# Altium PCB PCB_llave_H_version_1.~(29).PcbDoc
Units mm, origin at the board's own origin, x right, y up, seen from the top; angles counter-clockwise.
Board outline 232.16 x 155.45 mm, 2 copper layers (Top Layer, Bottom Layer); 51 components, 32 nets, 157 pads, 0 vias.
Unrouted connection lines stored in the file: 57.
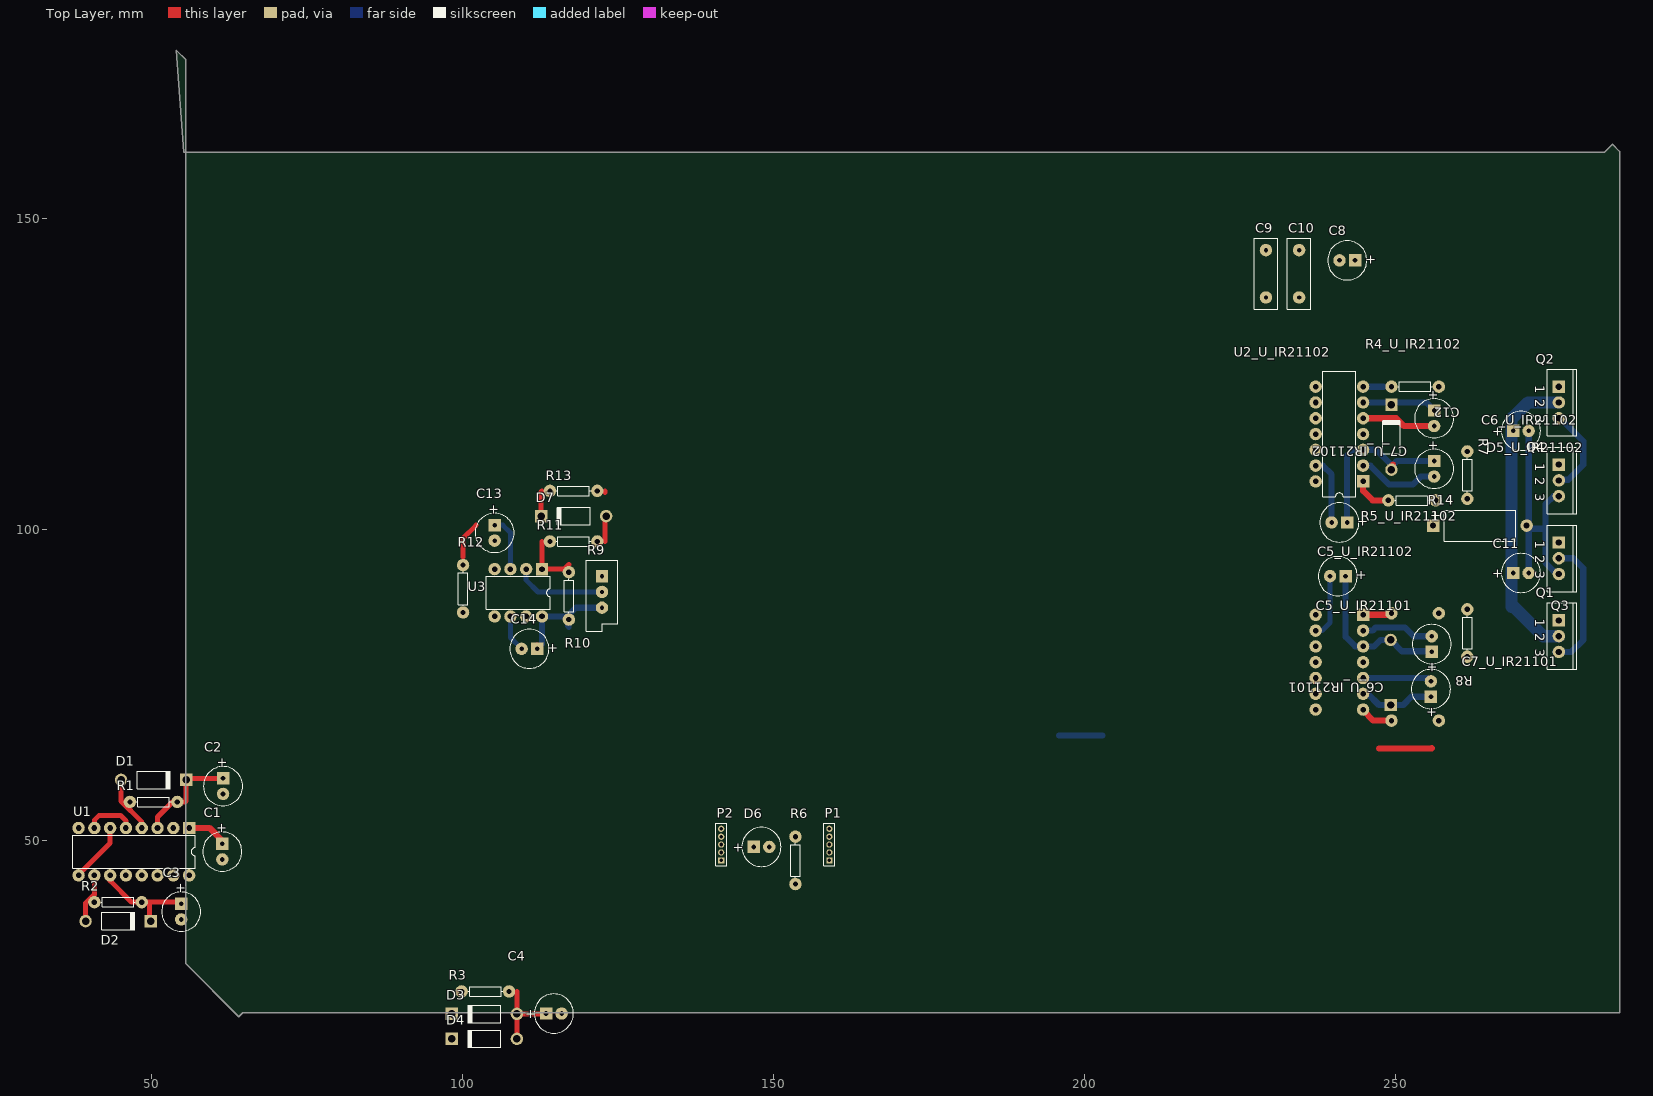
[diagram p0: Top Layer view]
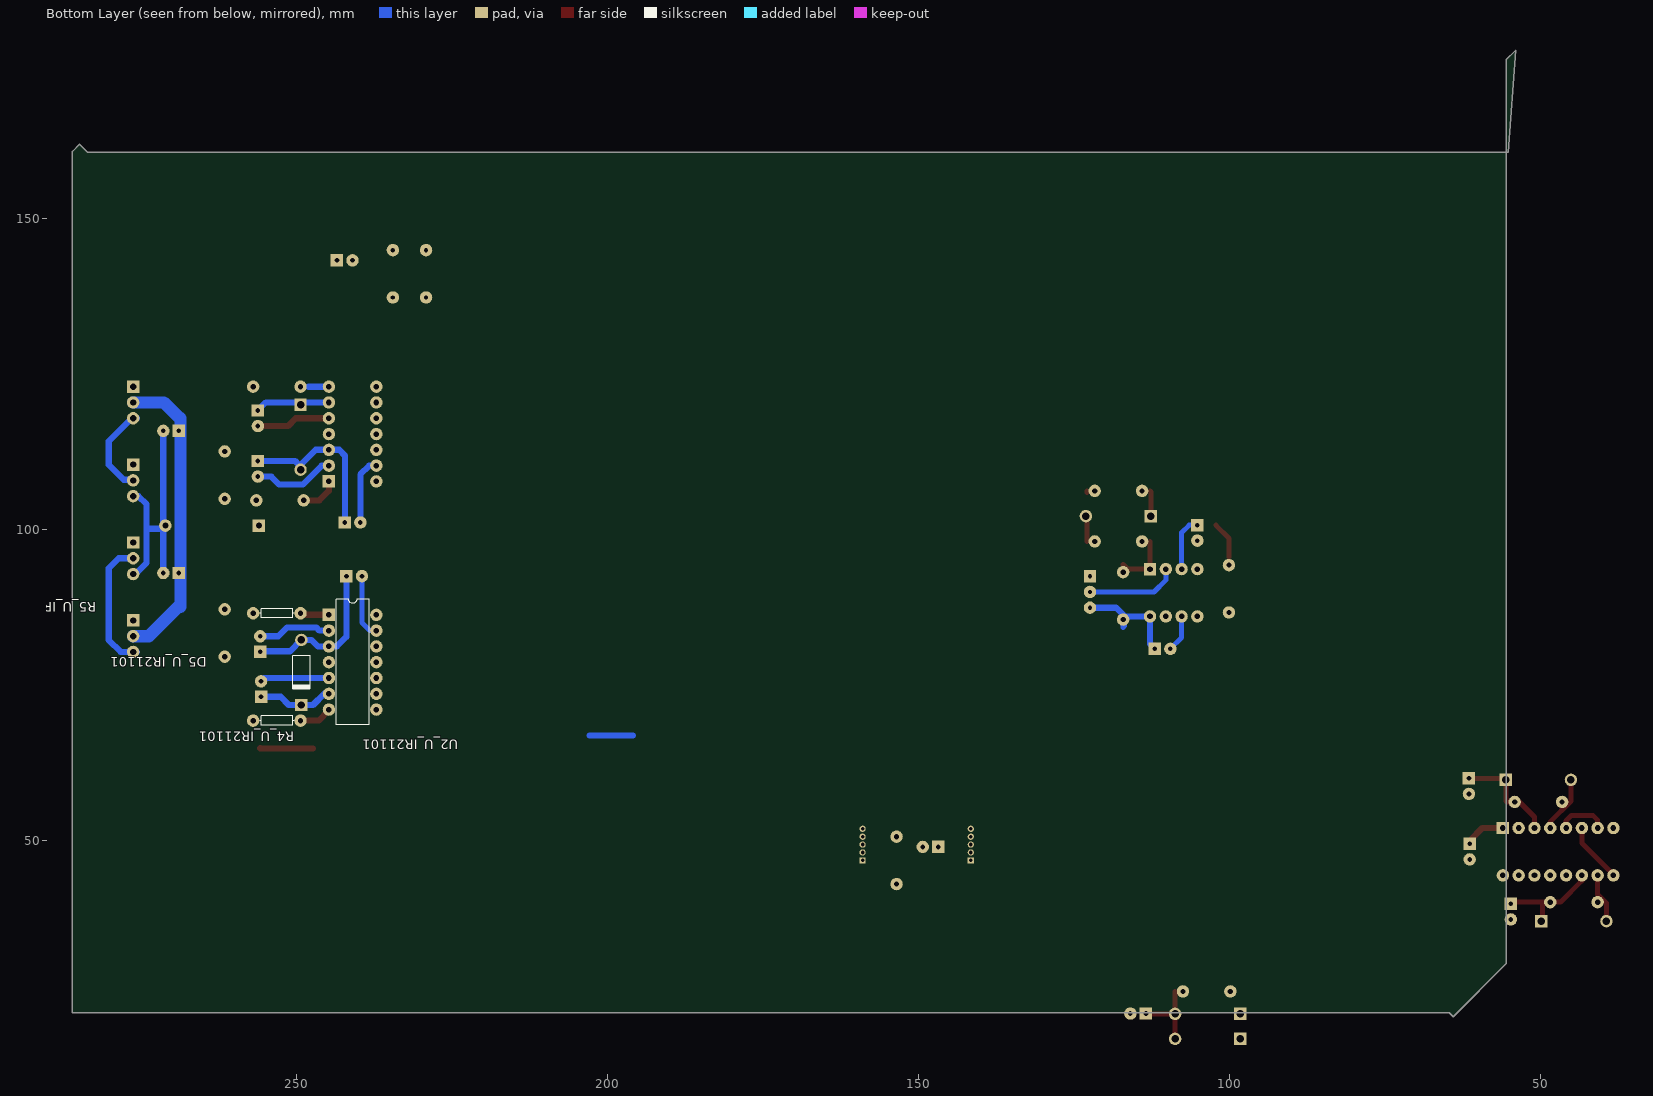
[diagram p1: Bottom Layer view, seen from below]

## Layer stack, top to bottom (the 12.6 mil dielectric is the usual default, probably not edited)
Top Layer: signal copper 0.0356
Dielectric: dielectric 0.32, FR-4, Dk 4.8
Bottom Layer: signal copper 0.0356

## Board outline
53.975,177.038 55.499,175.514 55.499,30.099 64.008,21.59 64.643,22.225 286.131,22.225 286.131,160.782 284.988,161.925 283.718,160.655 55.118,160.655

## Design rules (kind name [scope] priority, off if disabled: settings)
Clearance [All] p1: gap=0.4
ComponentClearance [All] p1: gap=0.254 collisioncheckmode=2 verticalgap=0.254
PolygonConnect [All] p1: connectstyle=Relief reliefconductorwidth=0.254 reliefentries=4 polygonreliefangle="90 Angle"
RoomDefinition U_IR21102 [InComponentClass('U_IR21102')] p1: confinementstyle=ConfineIn formatcopy=TRUE lockcomponents=FALSE outline 233.934,127 260.731,127 260.731,97.282 233.934,97.282
RoomDefinition U_Puente_H [InComponentClass('U_Puente_H')] p2: confinementstyle=ConfineOut formatcopy=TRUE lockcomponents=FALSE outline 287.274,23.114 304.927,23.114 304.927,32.512 287.274,32.512
RoomDefinition U_INITShutdown [InComponentClass('U_INITShutdown')] p3: confinementstyle=ConfineIn formatcopy=TRUE lockcomponents=FALSE outline 90.297,32.893 141.097,32.893 141.097,13.97 90.297,13.97
RoomDefinition U_Shutdown [InComponentClass('U_Shutdown')] p4: confinementstyle=ConfineOut formatcopy=TRUE lockcomponents=FALSE outline 65.913,145.923 116.713,145.923 116.713,121.92 65.913,121.92
RoomDefinition Llave_H_esquema [InComponentClass('Llave_H_esquema')] p5: confinementstyle=ConfineIn formatcopy=TRUE lockcomponents=FALSE outline 140.462,38.481 160.782,38.481 160.782,55.499 140.462,55.499
RoomDefinition U_4049 [InComponentClass('U_4049')] p6: confinementstyle=ConfineIn formatcopy=TRUE lockcomponents=FALSE outline 27.813,33.147 69.469,33.147 69.469,65.913 27.813,65.913
RoomDefinition U_IR21101 [InComponentClass('U_IR21101')] p7: confinementstyle=ConfineIn formatcopy=TRUE lockcomponents=FALSE outline 233.934,96.393 260.731,96.393 260.731,65.786 233.934,65.786
RoutingVias [All] p1: holewidth=0.711 width=1.27 viastyle="Through Hole" minholewidth=0.711 minwidth=1.27 maxholewidth=0.711 maxwidth=1.27
SolderMaskExpansion [All] p1: expansion=0.102
TestPointUsage [All] p1: valid=0 allowmultiple=FALSE
Testpoint [All] p1: side=15 testpointundercomponent=TRUE minsize=1.016 maxsize=2.54 preferedsize=1.524 minholesize=0 maxholesize=1.016 preferedholesize=0.813 testpointgrid=0.025 style=1023 order=0-112345678
Width [All] p1: maxlimit=3 minlimit=0.8 preferedwidth=1
18 further rules are at their usual default settings.

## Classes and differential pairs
component class U_INITShutdown: C4 D3 D4 R3
channel class IR2110: U_IR21101 U_IR21102
component class U_Shutdown: C13 C14 D7 R9 R10 R11 R12 R13 R14 U3
component class U_Puente_H: C8 C9 C10 C11 C12 Q1 Q2 Q3 Q4 R7 R8
component class U_IR21102: C5_U_IR21102 C6_U_IR21102 C7_U_IR21102 D5_U_IR21102 R4_U_IR21102 R5_U_IR21102 U2_U_IR21102
component class U_IR21101: C5_U_IR21101 C6_U_IR21101 C7_U_IR21101 D5_U_IR21101 R4_U_IR21101 R5_U_IR21101 U2_U_IR21101
component class U_4049: C1 C2 C3 D1 D2 R1 R2 U1
component class Llave_H_esquema: D6 P1 P2 R6

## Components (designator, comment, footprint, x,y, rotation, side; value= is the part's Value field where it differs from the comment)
C1 "Cap Pol1" CAPPR2.5-6.3X5 61.341,48.133 r270 top
C2 "Cap Pol1" CAPPR2.5-6.3X5 61.468,58.674 r270 top
C3 "Cap Pol1" CAPPR2.5-6.3X5 54.737,38.481 r270 top
C4 "Cap Pol1" CAPPR2.5-6.3X5 114.681,22.098 r0 top
C5_U_IR21101 "Cap Pol1" CAPPR2.5-6.3X5 240.792,92.456 r180 top (schematic designator C5)
C5_U_IR21102 "Cap Pol1" CAPPR2.5-6.3X5 241.046,101.092 r180 top (schematic designator C5)
C6_U_IR21101 "Cap Pol1" CAPPR2.5-6.3X5 255.778,74.295 r90 top (schematic designator C6)
C6_U_IR21102 "Cap Pol1" CAPPR2.5-6.3X5 256.286,117.856 r270 top (schematic designator C6)
C7_U_IR21101 "Cap Pol1" CAPPR2.5-6.3X5 255.905,81.534 r90 top (schematic designator C7)
C7_U_IR21102 "Cap Pol1" CAPPR2.5-6.3X5 256.286,109.728 r270 top (schematic designator C7)
C8 "Cap Pol1" CAPPR2.5-6.3X5 242.316,143.256 r180 top
C9 "Cap" RAD-0.3 229.235,141.097 r90 top
C10 "Cap" RAD-0.3 234.569,141.097 r90 top
C11 "Cap Pol1" CAPPR2.5-6.3X5 270.256,92.964 r0 top
C12 "Cap Pol1" CAPPR2.5-6.3X5 270.256,115.824 r0 top
C13 "Cap Pol1" CAPPR2.5-6.3X5 105.156,99.421 r270 top
C14 "Cap Pol1" CAPPR2.5-6.3X5 110.744,80.772 r180 top
D1 "Diode" DO-204AL 50.292,59.69 r0 top
D2 "Diode" DO-204AL 44.577,36.957 r0 top
D3 "Diode" DO-204AL 103.505,22.036 r180 top
D4 "Diode" DO-204AL 103.505,18.034 r180 top
D5_U_IR21101 "Diode" DO-204AL 249.301,76.962 r270 bottom (schematic designator D5)
D5_U_IR21102 "Diode" DO-204AL 249.428,114.808 r90 top (schematic designator D5)
D6 "LED0" CAPPR2.5-6.3X5 148.082,48.895 r0 top
D7 "Diode" DO-204AL 117.856,102.108 r180 top
P1 "MHDR1X5" MHDR1X5 159.004,46.736 r90 top
P2 "MHDR1X5" MHDR1X5 141.605,46.736 r90 top
Q1 "IRF3205" TO-220AB 276.352,82.804 r270 top
Q2 "IRF3205" TO-220AB 276.352,120.396 r270 top
Q3 "IRF3205" TO-220AB 276.352,95.335 r270 top
Q4 "IRF3205" TO-220AB 276.352,107.865 r270 top
R1 "Res2" AXIAL-0.3 50.292,56.134 r180 top
R2 "Res2" AXIAL-0.3 44.577,40.005 r0 top
R3 "Res2" AXIAL-0.3 103.661,25.654 r180 top
R4_U_IR21101 "Res2" AXIAL-0.3 253.238,69.215 r0 bottom (schematic designator R4)
R4_U_IR21102 "Res2" AXIAL-0.3 253.238,122.936 r0 top (schematic designator R4)
R5_U_IR21101 "Res2" AXIAL-0.3 253.238,86.487 r0 bottom (schematic designator R5)
R5_U_IR21102 "Res2" AXIAL-0.3 252.73,104.648 r0 top (schematic designator R5)
R6 "Res2" AXIAL-0.3 153.543,46.736 r90 top
R7 "Res2" AXIAL-0.3 261.62,108.712 r270 top
R8 "Res2" AXIAL-0.3 261.62,83.312 r90 top
R9 "RPot" VR5 122.428,89.916 r270 top
R10 "Res2" AXIAL-0.3 117.094,89.281 r270 top
R11 "Res2" AXIAL-0.3 117.856,98.044 r0 top
R12 "Res2" AXIAL-0.3 100.076,90.424 r90 top
R13 "Res2" AXIAL-0.3 117.856,106.172 r180 top
R14 "Res2" CAPPA15.05-11.5x5 263.652,100.584 r0 top
U1 "MC54HC4049J" 620-09 47.117,48.133 r180 top
U2_U_IR21101 "IR2110" PDIP14 241.046,78.613 r270 bottom (schematic designator U2)
U2_U_IR21102 "IR2110" PDIP14 241.046,115.316 r90 top (schematic designator U2)
U3 "LM393N" 626-05 108.966,89.789 r180 top

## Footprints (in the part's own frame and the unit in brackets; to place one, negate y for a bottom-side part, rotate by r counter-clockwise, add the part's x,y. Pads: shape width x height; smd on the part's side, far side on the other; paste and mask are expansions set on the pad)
620-09 [mm] "DIP; 16 Leads; Row Spacing 7.62 mm; Pitch 2.54 mm"
  rect 2x2 hole 0.9: 1(-8.89,-3.81)
  round 2 hole 0.9: 2(-6.35,-3.81) 3(-3.81,-3.81) 4(-1.27,-3.81) 5(1.27,-3.81) 6(3.81,-3.81) 7(6.35,-3.81) 8(8.89,-3.81) 9(8.89,3.81) 10(6.35,3.81) 11(3.81,3.81) 12(1.27,3.81) 13(-1.27,3.81) 14(-3.81,3.81) 15(-6.35,3.81) 16(-8.89,3.81)
  silkscreen extent -9.85,-2.65 9.85,2.65
626-05 [mm] "DIP; 8 Leads; Row Spacing 7.62 mm; Pitch 2.54 mm"
  rect 2x2 hole 0.9: 1(-3.81,-3.81)
  round 2 hole 0.9: 2(-1.27,-3.81) 3(1.27,-3.81) 4(3.81,-3.81) 5(3.81,3.81) 6(1.27,3.81) 7(-1.27,3.81) 8(-3.81,3.81)
  silkscreen extent -5.15,-2.65 5.15,2.65
AXIAL-0.3 [mm] "Resistor; 2 Leads"
  round 2 hole 0.85: 1(-3.81,0) 2(3.81,0)
  silkscreen extent -2.77,-0.76 2.77,0.76
CAPPA15.05-11.5x5 [mm] "Capacitor, Electrolytic, Axial; Body 11.5 x 5 mm (LxDia. max), Lead Dia. 0.6 mm (typ)"
  rect 2x2 hole 0.95: 1(-7.525,0)
  round 2 hole 0.95: 2(7.525,0)
  silkscreen extent -5.75,-2.5 5.75,2.5
CAPPR2.5-6.3X5 [mm] "Capacitor, Electrolytic, Radial; Body 6.3 x 5 mm (Dia.xH typ); Pin Spacing 2.5 mm (typ)"
  rect 2x2 hole 0.75: 1(-1.25,0)
  round 2 hole 0.75: 2(1.25,0)
  silkscreen extent -3.15,-3.15 3.15,3.15
DO-204AL [mm] "Diode, Axial; Body 5.2 x 2.7 mm (LxDia. max), Lead Dia. 0.86 mm (max)"
  round 2 hole 1.2: 1(-5.23,0)
  rect 2x2 hole 1.2: 2(5.23,0)
  silkscreen extent -2.65,-1.4 2.75,1.4
MHDR1X5 [mm] "Connector; Header; 5 Position"
  rect 1x1 hole 0.6: 1(0,0)
  round 1 hole 0.6: 2(1.27,0) 3(2.54,0) 4(3.81,0) 5(5.08,0)
  silkscreen extent -0.9,-0.9 5.98,0.9
PDIP14 [mm] "DIP; 14 Leads; Row Spacing 7.62 mm; Pitch 2.54 mm"
  rect 2x2 hole 0.9: 1(-7.62,-3.81)
  round 2 hole 0.9: 2(-5.08,-3.81) 3(-2.54,-3.81) 4(0,-3.81) 5(2.54,-3.81) 6(5.08,-3.81) 7(7.62,-3.81) 8(7.62,3.81) 9(5.08,3.81) 10(2.54,3.81) 11(0,3.81) 12(-2.54,3.81) 13(-5.08,3.81) 14(-7.62,3.81)
  silkscreen extent -10.1,-2.65 10.1,2.65
RAD-0.3 [mm] "Capacitor; 2 Leads"
  round 2 hole 0.7: 1(-3.81,0) 2(3.81,0)
  silkscreen extent -5.71,-1.91 5.71,1.91
TO-220AB [mm] "TO, Thru-Hole, Vertical, Heatsink Mounted; 3 In-Line Leads; Pitch 2.54 mm"
  rect 2x2 hole 1: 1(-2.54,0)
  round 2 hole 1: 2(0,0) 3(2.54,0)
  silkscreen extent -5.35,-1.85 5.35,2.85
VR5 [mm] "Potentiometer; 3 Leads"
  rect 2x2 hole 0.7: 1(-2.54,0)
  round 2 hole 0.7: 2(2.54,0) 3(0,0)
  silkscreen extent -5.08,-2.54 6.35,2.54

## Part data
C1 C2 C3 C4 C5_U_IR21101 C5_U_IR21102 C6_U_IR21101 C6_U_IR21102 C7_U_IR21101 C7_U_IR21102 C8 C11 C12 C13 C14: "Polarized Capacitor (Radial)"
C9 C10: "Capacitor"
D1 D2 D3 D4 D5_U_IR21101 D5_U_IR21102 D7: "Default Diode"
D6: "Typical INFRARED GaAs LED"
P1 P2: "Header, 5-Pin"
Q1 Q2 Q3 Q4: "HEXFET Power MOSFET"
R1 R2 R3 R4_U_IR21101 R4_U_IR21102 R5_U_IR21101 R5_U_IR21102 R6 R7 R8 R10 R11 R12 R13 R14: "Resistor"
R9: "Potentiometer"
U1: "Hex Inverting Buffer/Logic-Level Down Converter"
U2_U_IR21101 U2_U_IR21102: "High and Low Side Driver"
U3: "Dual Comparator"

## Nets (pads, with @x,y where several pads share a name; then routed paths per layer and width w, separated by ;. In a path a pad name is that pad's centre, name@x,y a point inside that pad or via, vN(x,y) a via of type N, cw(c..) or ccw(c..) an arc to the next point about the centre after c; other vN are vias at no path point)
COM_U_IR21101: C7_U_IR21101.2 C7_U_IR21102.2 C11.2 C12.2 Q3.3 Q4.3 R7.1 R8.1 R12.1 R14.2 U2_U_IR21101.2 U2_U_IR21102.2 | length 81.3
  Top Layer w1: 247.416,64.75 255.885,64.75 255.905,64.77
  Bottom Layer w1: 195.981,66.822 202.926,66.822 ; U2_U_IR21101.2 246.38,83.693 246.888,84.201 251.587,84.201 253.004,82.784 C7_U_IR21101.2 ; U2_U_IR21102.2 245.999,110.236 249.047,107.188 252.857,107.188 254.147,108.478 C7_U_IR21102.2 ; C11.2 C12.2 ; R14.2@271.506,100.076 274.193,100.076 ; Q4.3 275.505,105.325 274.193,104.013 274.193,94.615 276.013,92.795 Q3.3@276.564,92.795
GND: C1.2 C2.2 C3.2 C4.2 C5_U_IR21101.2 C5_U_IR21102.2 C8.2 C9.1 C10.1 C13.2 C14.2 D6.2 P1.1 P2.4 R9.1 R13.1 R14.1 U1.8 U2_U_IR21101.13 U2_U_IR21102.13 U3.4 U3.5 U3.6 | length 27.5
  Top Layer w0.8: U3.5 105.176,85.999 U3.5@105.156,86.019 ; U3.6@107.676,85.999 U3.6 ; 122.936,105.918 122.936,106.172
  Bottom Layer w0.8: U3.6 107.696,82.57 C14.2 ; U2_U_IR21101.13 238.252,83.693 239.542,84.983 C5_U_IR21101.2
  Bottom Layer w1: U2_U_IR21102.13 238.379,110.236 239.796,108.819 C5_U_IR21102.2
HIN_U_IR21101: U1.12 U2_U_IR21101.10 U2_U_IR21102.12
HIN_U_IR21102: U1.2 U2_U_IR21101.12 U2_U_IR21102.10
HO1: Q2.1 R4_U_IR21102.2
HO2: Q1.1 R4_U_IR21101.2
IN_SD: D4.2 P2.3
LO1: Q4.1 R5_U_IR21102.2 R7.2
LO2: Q3.1 R5_U_IR21101.2 R8.2
MOTOR+: C6_U_IR21102.2 Q2.3 Q4.2 U2_U_IR21102.5 | length 26.7
  Top Layer w1: U2_U_IR21102.5 250.19,117.856 251.44,116.606 C6_U_IR21102.2
  Bottom Layer w1: Q2.3@275.717,117.856 276.606,117.856 280.289,114.173 280.289,110.363 277.876,107.95 Q4.2@276.437,107.95
MOTOR-: C6_U_IR21101.2 Q1.3 Q3.2 U2_U_IR21101.5 | length 32.7
  Bottom Layer w1: U2_U_IR21101.5 255.25,76.073 C6_U_IR21101.2 ; Q1.3@275.717,80.264 278.384,80.264 280.289,82.169 280.289,93.726 278.68,95.335 Q3.2
NetC2_1: C2.1 D1.2 R1.1 U1.3 | length 16.9
  Top Layer w0.8: U1.3 50.927,53.721 53.34,56.134 55.372,56.134 55.522,56.284 D1.2 55.756,59.924 C2.1
NetC3_1: C3.1 D2.2 R2.2 U1.11 | length 17
  Top Layer w0.8: U1.11 43.307,43.434 46.736,40.005 54.463,40.005 C3.1 ; 49.657,40.005 49.657,37.107 D2.2
NetC4_1: C4.1 D3.1 D4.1 R3.1 | length 12.8
  Top Layer w0.8: D3.1@108.429,22.342 D3.1 113.369,22.036 C4.1 ; D4.1 108.741,18.04 108.741,25.654
NetC6_U_IR21101_1: C6_U_IR21101.1 D5_U_IR21101.2 U2_U_IR21101.6 | length 12.2
  Bottom Layer w1: U2_U_IR21101.6 245.618,73.533 247.419,71.732 251.31,71.732 252.623,73.045 C6_U_IR21101.1
NetC6_U_IR21102_1: C6_U_IR21102.1 D5_U_IR21102.2 U2_U_IR21102.6 | length 12.2
  Top Layer w0.8: D5_U_IR21102.2@249.532,120.396 D5_U_IR21102.2@249.682,120.546
  Bottom Layer w1: U2_U_IR21102.6 254.996,120.396 C6_U_IR21102.1
NetC13_1: C13.1 R12.2 U3.3 | length 15.1
  Top Layer w0.8: 100.076,95.504 100.076,98.552 102.195,100.671 ; C13.1 C13.1@105.243,100.584
  Bottom Layer w0.8: C13.1 106.466,100.671 107.696,99.441 U3.3
NetD1_1: D1.1 R1.2 U1.4 | length 9.1
  Top Layer w0.8: D1.1 45.062,56.284 48.387,52.959 U1.4
NetD2_1: D2.1 R2.1 U1.10 | length 8
  Top Layer w0.8: D2.1 39.347,39.855 40.767,41.275 U1.10
NetD6_1: D6.1 R6.1
NetD7_1: D7.1 R11.2 | length 4.2
  Top Layer w0.8: 122.936,98.044 D7.1@122.936,102.235
NetR4_U_IR21101_1: R4_U_IR21101.1 U2_U_IR21101.7 | length 5.4
  Top Layer w1: U2_U_IR21101.7 244.856,70.866 246.507,69.215 R4_U_IR21101.1
NetR4_U_IR21102_1: R4_U_IR21102.1 U2_U_IR21102.7 | length 3.3
  Bottom Layer w1: U2_U_IR21102.7 248.158,122.936
NetR5_U_IR21101_1: R5_U_IR21101.1 U2_U_IR21101.1 | length 4.7
  Top Layer w1: U2_U_IR21101.1 249.174,86.233 R5_U_IR21101.1
NetR5_U_IR21102_1: R5_U_IR21102.1 U2_U_IR21102.1 | length 6.2
  Top Layer w1: U2_U_IR21102.1 244.856,106.172 246.38,104.648 R5_U_IR21102.1
NetR9_3: R9.3 U3.2 | length 14.8
  Bottom Layer w0.8: U3.2 110.236,91.821 112.141,89.916 R9.3
NetR10_1: R10.1 R11.1 U3.1 | length 9.1
  Top Layer w0.8: 112.776,98.044 U3.1 116.332,93.599 117.094,94.361
NetU1_6: U1.6 U1.9 | length 9.7
  Top Layer w0.8: U1.9 38.227,44.45 43.307,49.53 U1.6
PWM: P2.2 U1.5 U1.7 | length 8.2
  Top Layer w0.8: U1.7 40.767,53.213 41.529,53.975 44.958,53.975 45.847,53.086 U1.5
SD: D3.2 D7.2 R13.2 U2_U_IR21101.11 U2_U_IR21102.11 | length 4.1
  Top Layer w0.8: D7.2 112.626,106.022 112.776,106.172
VCC_MOTOR: C8.1 C9.2 C10.2 C11.1 C12.1 P1.2 Q1.2 Q2.2 | length 48.1
  Bottom Layer w2: 268.732,87.503 268.732,117.876 ; 269.006,87.63 273.832,82.804 Q1.2 ; 269.006,118.003 271.399,120.396 Q2.2
VDD: C1.1 C5_U_IR21101.1 C5_U_IR21102.1 C7_U_IR21101.1 C7_U_IR21102.1 C14.1 D5_U_IR21101.1 D5_U_IR21102.1 P2.5 R3.2 R6.2 R9.2 R10.2 U1.1 U2_U_IR21101.3 U2_U_IR21101.9 U2_U_IR21102.3 U2_U_IR21102.9 U3.8 | length 79.9
  Top Layer w0.8: C1.1 C1.1@61.341,49.784 ; C14.1 C14.1@111.994,81.387 ; U3.8@112.649,86.233 112.776,86.106 U3.8
  Top Layer w1: U1.1 59.309,51.943 61.341,49.911 C1.1 ; D5_U_IR21102.1@249.682,110.086 D5_U_IR21102.1@249.682,110.363
  Bottom Layer w0.8: R10.2@116.84,85.979 116.84,84.455 117.094,84.201 117.094,86.198 R10.2@117.076,86.215
  Bottom Layer w1: C14.1 112.776,81.554 U3.8 R10.2@116.84,85.979 ; R10.2@117.076,86.215 118.237,87.376 R9.2 ; C5_U_IR21101.1 242.042,82.697 243.586,81.153 246.634,81.153 247.673,82.192 D5_U_IR21101.1 251.102,80.391 255.798,80.391 C7_U_IR21101.1 ; C5_U_IR21102.1 242.296,111.867 243.205,112.776 U2_U_IR21102.3 246.992,112.776 249.682,110.086 249.682,110.363 250.297,110.978 C7_U_IR21102.1
pads on no net: P1.3 P1.4 P1.5 P2.1 U1.13 U1.14 U1.15 U1.16 U2_U_IR21101.4 U2_U_IR21101.8 U2_U_IR21101.14 U2_U_IR21102.4 U2_U_IR21102.8 U2_U_IR21102.14 U3.7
